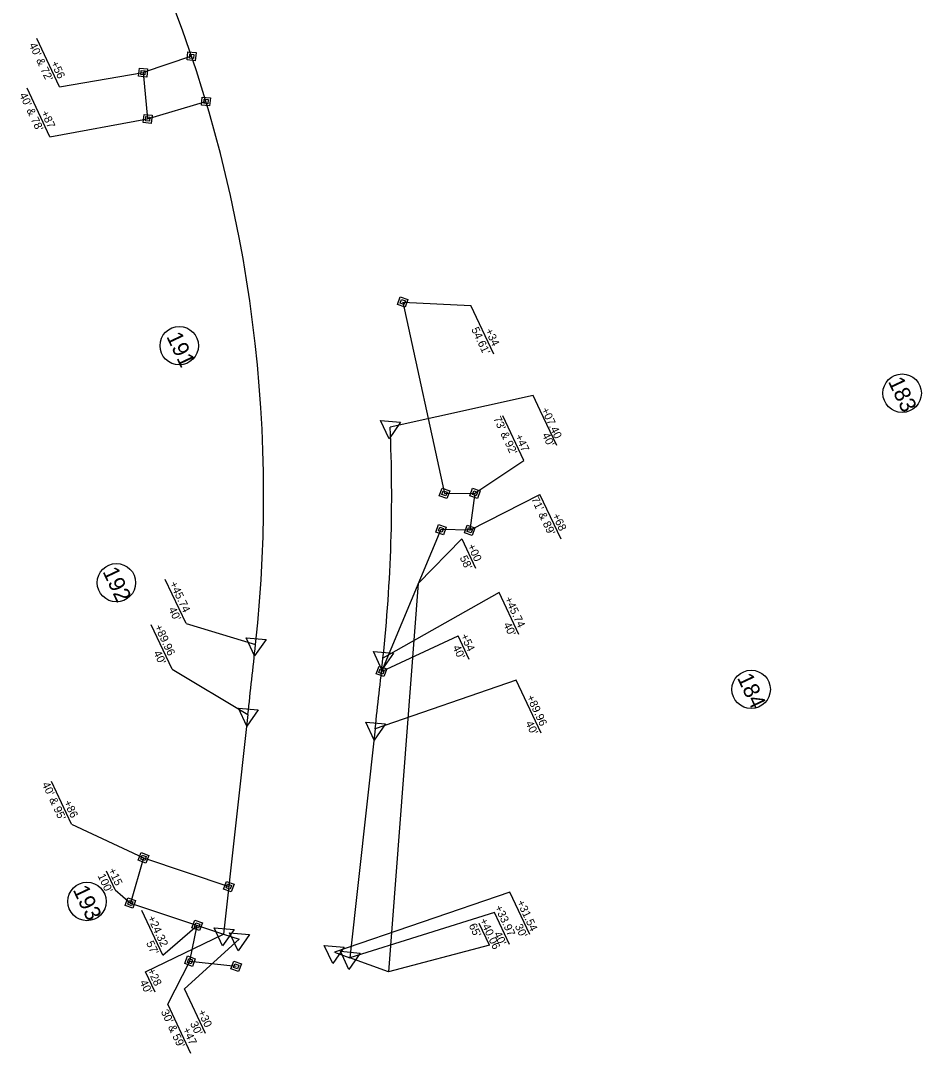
# Model space of a CAD drawing. Extents: x 2320946 to 2332748, y 597838 to 612698.
# Drawn here: x 2327236 to 2327799, y 600476 to 601121 of the extents above; entities that cross this region are included whole.
import ezdxf

# ---------------------------------------------------------------- set-up
doc = ezdxf.new("R2010")
doc.units = 0
for name, color, linetype in [('Prop Easement Construction', 7, 'Continuous'), ('Prop Easement Construction Station Offsets', 7, 'Continuous'), ('Prop Easement Permanent Drainage', 7, 'Continuous'), ('Prop Easement Permanent Drainage Station Offsets', 7, 'Continuous'), ('Prop Easement Permanent Utility', 7, 'Continuous'), ('Prop Easement Permanent Utility Station Offsets', 7, 'Continuous'), ('Prop Parcel Number CELL', 7, 'Continuous'), ('Prop ROW Marker CELL', 7, 'Continuous'), ('Prop ROW Permanent Easement CELL', 7, 'Continuous'), ('Prop ROW RW Lines', 7, 'Continuous'), ('Prop ROW Station Offsets', 7, 'Continuous')]:
    doc.layers.add(name, color=color, linetype=linetype)

msp = doc.modelspace()

# ---------------------------------------------------------------- linework, layer by layer
at = {"layer": 'Prop Easement Construction'}
for p, q in [((2327484.26, 600768.95), (2327465.85, 600526.4)), ((2327465.85, 600526.4), (2327441.67, 600535.19))]:
    msp.add_line(p, q, dxfattribs=at)
at = {"layer": 'Prop Easement Construction Station Offsets'}
for p, q in [((2327511.55, 600796.89), (2327484.26, 600768.95)), ((2327511.55, 600796.89), (2327520.12, 600778.69)), ((2327528.88, 600543.07), (2327522.43, 600556.76))]:
    msp.add_line(p, q, dxfattribs=at)
msp.add_lwpolyline([(2327528.88, 600543.07), (2327465.85, 600526.4)], dxfattribs=at)
at = {"layer": 'Prop Easement Permanent Drainage'}
for p, q in [((2327312.77, 600597.73), (2327304.61, 600569.45)), ((2327312.77, 600597.73), (2327366.12, 600579.75)), ((2327304.61, 600569.45), (2327362.82, 600549.93))]:
    msp.add_line(p, q, dxfattribs=at)
at = {"layer": 'Prop Easement Permanent Drainage Station Offsets'}
for p, q in [((2327267.89, 600618.78), (2327255.36, 600645.37)), ((2327295.07, 600577.72), (2327289.61, 600589.3))]:
    msp.add_line(p, q, dxfattribs=at)
for points in [[(2327267.89, 600618.78), (2327312.77, 600597.73)], [(2327295.07, 600577.72), (2327304.61, 600569.45)]]:
    msp.add_lwpolyline(points, dxfattribs=at)
at = {"layer": 'Prop Easement Permanent Utility'}
for p, q in [((2327342.83, 601098.35), (2327312.5, 601088.14)), ((2327312.5, 601088.14), (2327315.39, 601059.24)), ((2327315.39, 601059.24), (2327351.8, 601070.12)), ((2327474.73, 600944.86), (2327500.83, 600825.36)), ((2327500.83, 600825.36), (2327519.83, 600825.39)), ((2327519.83, 600825.39), (2327516.6, 600802.31)), ((2327498.6, 600802.7), (2327461.45, 600714.15)), ((2327516.6, 600802.31), (2327498.6, 600802.7)), ((2327341.84, 600533.14), (2327346.32, 600555.46)), ((2327341.84, 600533.14), (2327370.67, 600529.95))]:
    msp.add_line(p, q, dxfattribs=at)
at = {"layer": 'Prop Easement Permanent Utility Station Offsets'}
for p, q in [((2327260.41, 601079.17), (2327246.1, 601109.55)), ((2327260.41, 601079.17), (2327312.5, 601088.14)), ((2327254.37, 601047.95), (2327240.06, 601078.33)), ((2327254.37, 601047.95), (2327315.39, 601059.24)), ((2327474.73, 600944.86), (2327517.26, 600942.73)), ((2327531.57, 600912.35), (2327517.26, 600942.73)), ((2327550.44, 600845.84), (2327537.29, 600873.75)), ((2327519.83, 600825.39), (2327550.44, 600845.84)), ((2327516.6, 600802.31), (2327560.45, 600824.56)), ((2327573.6, 600796.64), (2327560.45, 600824.56)), ((2327461.45, 600714.15), (2327509.31, 600736.31)), ((2327516.22, 600721.64), (2327509.31, 600736.31)), ((2327324.82, 600536.89), (2327311.68, 600564.81)), ((2327324.82, 600536.89), (2327346.32, 600555.46)), ((2327327.99, 600506.21), (2327341.84, 600533.14)), ((2327342.41, 600475.59), (2327327.99, 600506.21))]:
    msp.add_line(p, q, dxfattribs=at)
at = {"layer": 'Prop Parcel Number CELL'}
for p, q in [((2327335.13, 600917.59), (2327335.13, 600917.59)), ((2327786.65, 600887.92), (2327786.65, 600887.92)), ((2327295.88, 600769.53), (2327295.88, 600769.53)), ((2327692.34, 600702.91), (2327692.34, 600702.91)), ((2327277.49, 600570.44), (2327277.49, 600570.44))]:
    msp.add_line(p, q, dxfattribs=at)
for centre in [(2327335.13, 600917.59), (2327786.65, 600887.92), (2327295.88, 600769.53), (2327692.34, 600702.91), (2327277.49, 600570.44)]:
    msp.add_circle(centre, 12, dxfattribs=at)
at = {"layer": 'Prop ROW Marker CELL'}
for p, q in [((2327342.83, 601098.35), (2327342.83, 601098.35)), ((2327312.5, 601088.14), (2327312.5, 601088.14)), ((2327351.8, 601070.12), (2327351.8, 601070.12)), ((2327315.39, 601059.24), (2327315.39, 601059.24)), ((2327474.73, 600944.86), (2327474.73, 600944.86)), ((2327466.85, 600866.65), (2327466.85, 600866.65)), ((2327500.83, 600825.36), (2327500.83, 600825.36)), ((2327519.83, 600825.39), (2327519.83, 600825.39)), ((2327498.6, 600802.7), (2327498.6, 600802.7)), ((2327516.6, 600802.31), (2327516.6, 600802.31)), ((2327382.81, 600731), (2327382.81, 600731)), ((2327462.34, 600722.37), (2327462.34, 600722.37)), ((2327461.45, 600714.15), (2327461.45, 600714.15)), ((2327378, 600687.13), (2327378, 600687.13)), ((2327457.52, 600678.33), (2327457.52, 600678.33)), ((2327312.77, 600597.73), (2327312.77, 600597.73)), ((2327366.12, 600579.75), (2327366.12, 600579.75)), ((2327304.61, 600569.45), (2327304.61, 600569.45)), ((2327346.32, 600555.46), (2327346.32, 600555.46)), ((2327362.82, 600549.93), (2327362.82, 600549.93)), ((2327372.54, 600546.84), (2327372.54, 600546.84)), ((2327431.64, 600538.85), (2327431.64, 600538.85)), ((2327341.84, 600533.14), (2327341.84, 600533.14)), ((2327441.67, 600535.19), (2327441.67, 600535.19)), ((2327370.67, 600529.95), (2327370.67, 600529.95))]:
    msp.add_line(p, q, dxfattribs=at)
for points in [[(2327460.93, 600870.77), (2327473.37, 600869.72), (2327466.26, 600859.46)], [(2327376.89, 600735.12), (2327389.32, 600734.07), (2327382.22, 600723.81)], [(2327456.42, 600726.49), (2327468.86, 600725.44), (2327461.75, 600715.18)], [(2327372.08, 600691.26), (2327384.52, 600690.2), (2327377.41, 600679.95)], [(2327451.6, 600682.45), (2327464.03, 600681.4), (2327456.92, 600671.15)], [(2327356.9, 600554.05), (2327369.33, 600553), (2327362.22, 600542.74)], [(2327366.62, 600550.96), (2327379.05, 600549.91), (2327371.94, 600539.66)], [(2327425.72, 600542.97), (2327438.15, 600541.91), (2327431.05, 600531.66)], [(2327435.75, 600539.32), (2327448.19, 600538.26), (2327441.08, 600528.01)]]:
    msp.add_lwpolyline(points, close=True, dxfattribs=at)
at = {"layer": 'Prop ROW Permanent Easement CELL'}
for points in [[(2327340.55, 601101.14), (2327345.62, 601100.63), (2327345.1, 601095.56), (2327340.04, 601096.07)], [(2327341.69, 601099.75), (2327344.22, 601099.49), (2327343.97, 601096.96), (2327341.43, 601097.21)], [(2327310.23, 601090.92), (2327315.29, 601090.41), (2327314.78, 601085.35), (2327309.71, 601085.86)], [(2327311.36, 601089.53), (2327313.9, 601089.27), (2327313.64, 601086.74), (2327311.11, 601087)], [(2327349.52, 601072.91), (2327354.59, 601072.4), (2327354.08, 601067.33), (2327349.01, 601067.84)], [(2327350.66, 601071.52), (2327353.19, 601071.26), (2327352.94, 601068.73), (2327350.41, 601068.98)], [(2327313.12, 601062.03), (2327318.18, 601061.51), (2327317.67, 601056.45), (2327312.6, 601056.96)], [(2327314.25, 601060.63), (2327316.79, 601060.38), (2327316.53, 601057.84), (2327314, 601058.1)], [(2327477.99, 600946.39), (2327476.27, 600941.6), (2327471.48, 600943.32), (2327473.2, 600948.11)], [(2327476.36, 600945.62), (2327475.5, 600943.23), (2327473.1, 600944.09), (2327473.96, 600946.49)], [(2327504.09, 600826.89), (2327502.36, 600822.1), (2327497.57, 600823.82), (2327499.3, 600828.61)], [(2327523.09, 600826.92), (2327521.36, 600822.13), (2327516.57, 600823.85), (2327518.3, 600828.64)], [(2327502.46, 600826.12), (2327501.6, 600823.73), (2327499.2, 600824.59), (2327500.06, 600826.99)], [(2327521.46, 600826.15), (2327520.6, 600823.76), (2327518.2, 600824.62), (2327519.06, 600827.02)], [(2327501.86, 600804.23), (2327500.14, 600799.44), (2327495.35, 600801.17), (2327497.07, 600805.96)], [(2327500.23, 600803.47), (2327499.37, 600801.07), (2327496.97, 600801.93), (2327497.84, 600804.33)], [(2327519.85, 600803.84), (2327518.13, 600799.05), (2327513.34, 600800.77), (2327515.06, 600805.56)], [(2327518.23, 600803.07), (2327517.36, 600800.68), (2327514.97, 600801.54), (2327515.83, 600803.94)], [(2327464.71, 600715.68), (2327462.98, 600710.89), (2327458.19, 600712.61), (2327459.92, 600717.4)], [(2327463.08, 600714.91), (2327462.22, 600712.52), (2327459.82, 600713.38), (2327460.68, 600715.77)], [(2327316.03, 600599.26), (2327314.3, 600594.47), (2327309.51, 600596.19), (2327311.24, 600600.98)], [(2327314.4, 600598.49), (2327313.54, 600596.1), (2327311.14, 600596.96), (2327312, 600599.36)], [(2327369.37, 600581.28), (2327367.65, 600576.49), (2327362.86, 600578.22), (2327364.58, 600583.01)], [(2327367.74, 600580.52), (2327366.88, 600578.12), (2327364.49, 600578.98), (2327365.35, 600581.38)], [(2327307.87, 600570.99), (2327306.14, 600566.2), (2327301.35, 600567.92), (2327303.08, 600572.71)], [(2327306.24, 600570.22), (2327305.38, 600567.82), (2327302.98, 600568.69), (2327303.84, 600571.08)], [(2327349.58, 600557), (2327347.86, 600552.21), (2327343.07, 600553.93), (2327344.79, 600558.72)], [(2327347.95, 600556.23), (2327347.09, 600553.83), (2327344.7, 600554.7), (2327345.56, 600557.09)], [(2327345.1, 600534.67), (2327343.37, 600529.88), (2327338.58, 600531.6), (2327340.31, 600536.39)], [(2327343.47, 600533.9), (2327342.61, 600531.51), (2327340.21, 600532.37), (2327341.07, 600534.77)], [(2327373.92, 600531.48), (2327372.2, 600526.69), (2327367.41, 600528.41), (2327369.13, 600533.2)], [(2327372.29, 600530.71), (2327371.43, 600528.32), (2327369.04, 600529.18), (2327369.9, 600531.58)]]:
    msp.add_lwpolyline(points, close=True, dxfattribs=at)
at = {"layer": 'Prop ROW RW Lines'}
for p, q in [((2327378, 600687.13), (2327362.82, 600549.93)), ((2327457.52, 600678.33), (2327441.67, 600535.19)), ((2327362.82, 600549.93), (2327372.54, 600546.84)), ((2327432, 600538.71), (2327441.67, 600535.19))]:
    msp.add_line(p, q, dxfattribs=at)
for centre, radius, start, end in [((2326527.83, 600823.8), 860, 353.80575, 22.46921), ((2326527.83, 600823.8), 940, 353.80575, 2.61301), ((2306757.93, 602969.49), 20746, 353.683873, 353.805751), ((2306757.93, 602969.49), 20826, 353.683873, 353.805751)]:
    msp.add_arc(centre, radius, start, end, dxfattribs=at)
at = {"layer": 'Prop ROW Station Offsets'}
for p, q in [((2327570.89, 600855.34), (2327560.65, 600877.1)), ((2327339.35, 600744.14), (2327326.41, 600771.62)), ((2327534.94, 600763.51), (2327462.34, 600722.37)), ((2327547.31, 600737.23), (2327534.94, 600763.51)), ((2327339.35, 600744.14), (2327382.81, 600731)), ((2327330.66, 600715.51), (2327317.56, 600743.32)), ((2327330.66, 600715.51), (2327378, 600687.13)), ((2327545.54, 600708.69), (2327457.52, 600678.33)), ((2327561.13, 600675.58), (2327545.54, 600708.69)), ((2327541.58, 600576.17), (2327432, 600538.71)), ((2327554.03, 600549.73), (2327541.58, 600576.17)), ((2327532.09, 600563.65), (2327441.67, 600535.19)), ((2327541.5, 600543.67), (2327532.09, 600563.65)), ((2327320.13, 600513.81), (2327314.14, 600526.55)), ((2327351.61, 600487.93), (2327338.45, 600515.88))]:
    msp.add_line(p, q, dxfattribs=at)
for points in [[(2327560.65, 600877.1), (2327556.26, 600886.41), (2327466.85, 600866.65)], [(2327314.14, 600526.55), (2327362.82, 600549.93)], [(2327338.45, 600515.88), (2327372.54, 600546.84)]]:
    msp.add_lwpolyline(points, dxfattribs=at)

# ---------------------------------------------------------------- texts
at = {"layer": 'Prop Easement Construction Station Offsets'}
for s, p in [('+00 ', (2327515.01, 600792.48)), ("58'", (2327510.17, 600785.15)), ("65'", (2327515.82, 600555.44)), ('+40.06 ', (2327522.61, 600558.63))]:
    msp.add_text(s, height=5, rotation=295.21583, dxfattribs=at).set_placement(p)
at = {"layer": 'Prop Easement Permanent Drainage Station Offsets'}
for s, rotation, p in [("40' & 95'", 295.21583, (2327249.22, 600643.74)), ('+86', 295.21583, (2327262.87, 600632.36)), ('+15', 295.21417, (2327290.64, 600590.06)), ("100'", 295.21417, (2327284.03, 600586.49))]:
    msp.add_text(s, height=5, rotation=rotation, dxfattribs=at).set_placement(p)
at = {"layer": 'Prop Easement Permanent Utility Station Offsets'}
for s, p in [("40' & 72'", (2327241.12, 601105.46)), ('+56', (2327254.77, 601094.07)), ("40' & 78'", (2327235.08, 601074.23)), ('+87', (2327248.62, 601063.08)), ("54.61'", (2327517.38, 600927.81)), ('+34', (2327526.04, 600927.03)), ("73' & 92'", (2327531.15, 600872.12)), ('+47', (2327544.69, 600860.97)), ("71' & 89'", (2327554.82, 600821.85)), ('+68', (2327567.96, 600811.57)), ('+54', (2327510.69, 600736.32)), ("40'", (2327505.73, 600729.24)), ('+24.32', (2327315.19, 600560.28)), ("57'", (2327314.33, 600544.49)), ("30' & 59'", (2327323.51, 600501.64)), ('+47', (2327337.05, 600490.49))]:
    msp.add_text(s, height=5, rotation=295.21583, dxfattribs=at).set_placement(p)
at = {"layer": 'Prop Parcel Number CELL'}
for s, p in [('191', (2327326.91, 600923.33)), ('183', (2327777.67, 600895.24)), ('192', (2327287.05, 600776.56)), ('184', (2327683.39, 600710.18)), ('193', (2327268.52, 600577.76))]:
    msp.add_text(s, height=10, rotation=295.21417, dxfattribs=at).set_placement(p)
at = {"layer": 'Prop ROW Station Offsets'}
for s, rotation, p in [('+07.40', 295.21417, (2327561.09, 600877.63)), ("40' ", 295.21417, (2327561.59, 600861.89)), ('+45.74 ', 295.21583, (2327329, 600769.04)), ('+45.74 ', 295.21583, (2327538.19, 600759.53)), ("40'", 295.21583, (2327328.26, 600753.01)), ("40'", 295.21583, (2327537.45, 600743.51)), ('+89.96 ', 295.21583, (2327319.54, 600742.05)), ("40'", 295.21583, (2327318.9, 600725.8)), ('+89.96 ', 295.21583, (2327551.9, 600698.11)), ("40'", 295.21583, (2327551.26, 600681.86)), ('+31.54 ', 295.21583, (2327545.86, 600570.01)), ('+33.97', 295.21583, (2327531.99, 600566.8)), ("40'", 295.21583, (2327531.46, 600550.32)), ("30'", 295.21583, (2327544.6, 600555.07)), ('+28', 295.21417, (2327315.11, 600527.41)), ("40'", 295.21417, (2327310.27, 600520.09)), ('+30', 295.21417, (2327346.58, 600501.54)), ("30'", 295.21417, (2327341.74, 600494.21))]:
    msp.add_text(s, height=5, rotation=rotation, dxfattribs=at).set_placement(p)

doc.saveas('drawing.dxf')
